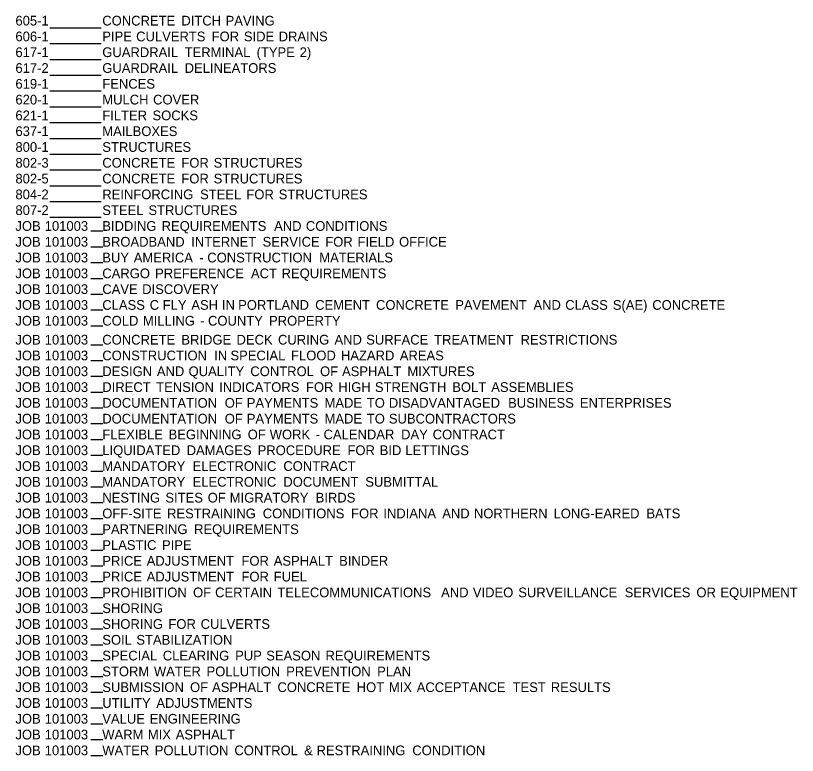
# Model space of a CAD drawing. Extents: x 2713 to 4149, y 471 to 1457.
# Drawn here: x 2714.3 to 3196.9, y 524 to 980.7 of the extents above; entities that cross this region are included whole.
import ezdxf

# ---------------------------------------------------------------- set-up
doc = ezdxf.new("R2010")
doc.units = 0
doc.layers.add('Default', color=7, linetype='Continuous')
doc.layers.add('R_Border', color=7, linetype='Continuous')

msp = doc.modelspace()

# ---------------------------------------------------------------- linework, layer by layer
at = {"layer": 'R_Border'}
for p, q in [((2735.51, 973.16), (2767.2, 973.16)), ((2735.51, 963.41), (2767.2, 963.41)), ((2735.51, 953.66), (2767.2, 953.66)), ((2735.51, 943.91), (2767.2, 943.91)), ((2735.51, 934.16), (2767.2, 934.16)), ((2735.51, 924.41), (2767.2, 924.41)), ((2735.51, 914.66), (2767.2, 914.66)), ((2735.51, 904.91), (2767.2, 904.91)), ((2735.51, 895.16), (2767.2, 895.16)), ((2735.51, 885.41), (2767.2, 885.41)), ((2735.51, 875.66), (2767.2, 875.66)), ((2735.51, 865.91), (2767.2, 865.91)), ((2735.51, 856.16), (2767.2, 856.16)), ((2760.77, 847.73), (2768.21, 847.73)), ((2760.77, 837.98), (2768.21, 837.98)), ((2760.77, 828.23), (2768.21, 828.23)), ((2760.77, 818.48), (2768.21, 818.48)), ((2760.77, 808.73), (2768.21, 808.73)), ((2760.77, 798.98), (2768.21, 798.98)), ((2760.77, 789.23), (2768.21, 789.23)), ((2760.77, 777.55), (2768.21, 777.55)), ((2760.77, 767.8), (2768.21, 767.8)), ((2760.77, 758.05), (2768.21, 758.05)), ((2760.77, 748.3), (2768.21, 748.3)), ((2760.77, 738.55), (2768.21, 738.55)), ((2760.77, 728.8), (2768.21, 728.8)), ((2760.77, 719.05), (2768.21, 719.05)), ((2760.77, 709.3), (2768.21, 709.3)), ((2760.77, 699.55), (2768.21, 699.55)), ((2760.77, 689.8), (2768.21, 689.8)), ((2760.77, 680.05), (2768.21, 680.05)), ((2760.77, 670.3), (2768.21, 670.3)), ((2760.77, 660.55), (2768.21, 660.55)), ((2760.77, 650.8), (2768.21, 650.8)), ((2760.77, 641.05), (2768.21, 641.05)), ((2760.77, 631.3), (2768.21, 631.3)), ((2760.77, 621.55), (2768.21, 621.55)), ((2760.77, 611.8), (2768.21, 611.8)), ((2760.77, 602.05), (2768.21, 602.05)), ((2760.77, 592.3), (2768.21, 592.3)), ((2760.77, 582.55), (2768.21, 582.55)), ((2760.77, 572.8), (2768.21, 572.8)), ((2760.77, 563.05), (2768.21, 563.05)), ((2760.77, 553.3), (2768.21, 553.3)), ((2760.77, 543.55), (2768.21, 543.55)), ((2760.77, 533.8), (2768.21, 533.8)), ((2760.77, 524.05), (2768.21, 524.05))]:
    msp.add_line(p, q, dxfattribs=at)

# ---------------------------------------------------------------- texts
at = {"layer": 'Default'}
for s, p in [('605-1', (2714.22, 974.57)), ('CONCRETE', (2767.84, 974.57)), (' DITCH', (2814.44, 974.57)), (' PAVING', (2841.71, 974.57)), ('606-1', (2714.22, 964.82)), ('PIPE', (2767.84, 964.82)), (' CULVERTS', (2786.5, 964.82)), (' FOR', (2833.11, 964.82)), (' SIDE', (2853.02, 964.82)), (' DRAINS', (2874.47, 964.82)), ('617-1', (2714.22, 955.07)), ('GUARDRAIL', (2767.84, 955.07)), (' TERMINAL', (2816.46, 955.07)), (' (TYPE', (2860.88, 955.07)), (' 2)', (2887.45, 955.07)), ('617-2', (2714.22, 945.32)), ('GUARDRAIL', (2767.84, 945.32)), (' DELINEATORS', (2816.46, 945.32)), ('619-1', (2714.22, 935.57)), ('FENCES', (2767.84, 935.57)), ('620-1', (2714.22, 925.82)), ('MULCH', (2767.84, 925.82)), (' COVER', (2796.97, 925.82)), ('621-1', (2714.22, 916.07)), ('FILTER', (2767.84, 916.07)), (' SOCKS', (2796.61, 916.07)), ('637-1', (2714.22, 906.32)), ('MAILBOXES', (2767.84, 906.32)), ('800-1', (2714.22, 896.57)), ('STRUCTURES', (2767.84, 896.57)), ('802-3', (2714.22, 886.82)), ('CONCRETE', (2767.84, 886.82)), (' FOR', (2814.44, 886.82)), (' STRUCTURES', (2834.35, 886.82)), ('802-5', (2714.22, 877.07)), ('CONCRETE', (2767.84, 877.07)), (' FOR', (2814.44, 877.07)), (' STRUCTURES', (2834.35, 877.07)), ('804-2', (2714.22, 867.32)), ('REINFORCING', (2767.84, 867.32)), (' STEEL', (2826, 867.32)), (' FOR', (2854.59, 867.32)), (' STRUCTURES', (2874.51, 867.32)), ('807-2', (2714.22, 857.57)), ('STEEL', (2767.84, 857.57)), (' STRUCTURES', (2794.1, 857.57)), ('JOB', (2714.22, 847.82)), (' 101003', (2730.08, 847.82)), ('BIDDING', (2767.84, 847.82)), (' REQUIREMENTS', (2802.25, 847.82)), (' AND', (2871.68, 847.82)), (' CONDITIONS', (2891.27, 847.82)), ('JOB', (2714.22, 838.07)), (' 101003', (2730.08, 838.07)), ('BROADBAND', (2767.84, 838.07)), (' INTERNET', (2820.51, 838.07)), (' SERVICE', (2864.59, 838.07)), (' FOR', (2903.27, 838.07)), (' FIELD', (2923.19, 838.07)), (' OFFICE', (2948.82, 838.07)), ('JOB', (2714.22, 828.32)), (' 101003', (2730.08, 828.32)), ('BUY', (2767.84, 828.32)), (' AMERICA', (2785.02, 828.32)), (' -', (2825.56, 828.32)), (' CONSTRUCTION', (2830.42, 828.32)), (' MATERIALS', (2899.59, 828.32)), ('JOB', (2714.22, 818.57)), (' 101003', (2730.08, 818.57)), ('CARGO', (2767.84, 818.57)), (' PREFERENCE', (2798.21, 818.57)), (' ACT', (2857.4, 818.57)), (' REQUIREMENTS', (2876.33, 818.57)), ('JOB', (2714.22, 808.82)), (' 101003', (2730.08, 808.82)), ('CAVE', (2767.84, 808.82)), (' DISCOVERY', (2790.23, 808.82)), ('JOB', (2714.22, 799.07)), (' 101003', (2730.08, 799.07)), ('CLASS', (2767.84, 799.07)), (' C', (2794.9, 799.07)), (' FLY', (2802.94, 799.07)), (' ASH', (2820.58, 799.07)), (' IN', (2839.47, 799.07)), (' PORTLAND', (2849.5, 799.07)), (' CEMENT', (2897.03, 799.07)), (' CONCRETE', (2934.59, 799.07)), (' PAVEMENT', (2983.52, 799.07)), (' AND', (3031.8, 799.07)), (' CLASS', (3051.39, 799.07)), (' S(AE)', (3080.77, 799.07)), (' CONCRETE', (3105.15, 799.07)), ('JOB', (2714.22, 789.32)), (' 101003', (2730.08, 789.32)), ('COLD', (2767.84, 789.32)), (' MILLING', (2790.68, 789.32)), (' -', (2826.02, 789.32)), (' COUNTY', (2830.88, 789.32)), (' PROPERTY', (2868.54, 789.32)), ('JOB', (2714.22, 777.62)), (' 101003', (2730.08, 777.62)), ('CONCRETE', (2767.84, 777.62)), (' BRIDGE', (2814.44, 777.62)), (' DECK', (2848.47, 777.62)), (' CURING', (2874.07, 777.62)), (' AND', (2908.94, 777.62)), (' SURFACE', (2928.52, 777.62)), (' TREATMENT', (2970.47, 777.62)), (' RESTRICTIONS', (3023.86, 777.62)), ('JOB', (2714.22, 767.87)), (' 101003', (2730.08, 767.87)), ('CONSTRUCTION', (2767.84, 767.87)), (' IN', (2834.69, 767.87)), (' SPECIAL', (2844.72, 767.87)), (' FLOOD', (2882.16, 767.87)), (' HAZARD', (2912.92, 767.87)), (' AREAS', (2949.27, 767.87)), ('JOB', (2714.22, 758.12)), (' 101003', (2730.08, 758.12)), ('DESIGN', (2767.84, 758.12)), (' AND', (2799.3, 758.12)), (' QUALITY', (2818.88, 758.12)), (' CONTROL', (2857.02, 758.12)), (' OF', (2900.04, 758.12)), (' ASPHALT', (2913.62, 758.12)), (' MIXTURES', (2953.99, 758.12)), ('JOB', (2714.22, 748.37)), (' 101003', (2730.08, 748.37)), ('DIRECT', (2767.84, 748.37)), (' TENSION', (2798.88, 748.37)), (' INDICATORS', (2837.79, 748.37)), (' FOR', (2891.38, 748.37)), (' HIGH', (2911.29, 748.37)), (' STRENGTH', (2933.9, 748.37)), (' BOLT', (2981.67, 748.37)), (' ASSEMBLIES', (3005.72, 748.37)), ('JOB', (2714.22, 738.62)), (' 101003', (2730.08, 738.62)), ('DOCUMENTATION', (2767.84, 738.62)), (' OF', (2841.21, 738.62)), (' PAYMENTS', (2854.8, 738.62)), (' MADE', (2902.81, 738.62)), (' TO', (2928.92, 738.62)), (' DISADVANTAGED', (2942.51, 738.62)), (' BUSINESS', (3016.14, 738.62)), (' ENTERPRISES', (3060.43, 738.62)), ('JOB', (2714.22, 728.87)), (' 101003', (2730.08, 728.87)), ('DOCUMENTATION', (2767.84, 728.87)), (' OF', (2841.21, 728.87)), (' PAYMENTS', (2854.8, 728.87)), (' MADE', (2902.81, 728.87)), (' TO', (2928.92, 728.87)), (' SUBCONTRACTORS', (2942.51, 728.87)), ('JOB', (2714.22, 719.12)), (' 101003', (2730.08, 719.12)), ('FLEXIBLE', (2767.84, 719.12)), (' BEGINNING', (2806.53, 719.12)), (' OF', (2855.38, 719.12)), (' WORK', (2868.97, 719.12)), (' CALENDAR', (2902.22, 719.12)), (' DAY', (2950.09, 719.12)), (' CONTRACT', (2969.59, 719.12)), (' -', (2897.36, 719.12)), ('JOB', (2714.22, 709.37)), (' 101003', (2730.08, 709.37)), ('LIQUIDATED', (2767.84, 709.37)), (' DAMAGES', (2817.7, 709.37)), (' PROCEDURE', (2861.52, 709.37)), (' FOR', (2916.98, 709.37)), (' BID', (2936.89, 709.37)), (' LETTINGS', (2952.74, 709.37)), ('JOB', (2714.22, 699.62)), (' 101003', (2730.08, 699.62)), ('MANDATORY', (2767.84, 699.62)), (' ELECTRONIC', (2821.35, 699.62)), (' CONTRACT', (2877.38, 699.62)), ('JOB', (2714.22, 689.87)), (' 101003', (2730.08, 689.87)), ('MANDATORY', (2767.84, 689.87)), (' ELECTRONIC', (2821.35, 689.87)), (' DOCUMENT', (2877.38, 689.87)), (' SUBMITTAL', (2927.97, 689.87)), ('JOB', (2714.22, 680.12)), (' 101003', (2730.08, 680.12)), ('NESTING', (2767.84, 680.12)), (' SITES', (2804.58, 680.12)), (' OF', (2830.7, 680.12)), (' MIGRATORY', (2844.29, 680.12)), (' BIRDS', (2897.32, 680.12)), ('JOB', (2714.22, 670.37)), (' 101003', (2730.08, 670.37)), ('OFF-SITE', (2767.84, 670.37)), (' RESTRAINING', (2805.58, 670.37)), (' CONDITIONS', (2864.68, 670.37)), (' FOR', (2919.2, 670.37)), (' INDIANA', (2939.11, 670.37)), (' AND', (2975.46, 670.37)), (' NORTHERN', (2995.04, 670.37)), (' LONG-EARED', (3044.2, 670.37)), (' BATS', (3101.51, 670.37)), ('JOB', (2714.22, 660.62)), (' 101003', (2730.08, 660.62)), ('PARTNERING', (2767.84, 660.62)), (' REQUIREMENTS', (2822.28, 660.62)), ('JOB', (2714.22, 650.87)), (' 101003', (2730.08, 650.87)), ('PLASTIC', (2767.84, 650.87)), (' PIPE', (2802.45, 650.87)), ('JOB', (2714.22, 641.12)), (' 101003', (2730.08, 641.12)), ('PRICE', (2767.84, 641.12)), (' ADJUSTMENT', (2793.02, 641.12)), (' FOR', (2851.54, 641.12)), (' ASPHALT', (2871.45, 641.12)), (' BINDER', (2911.82, 641.12)), ('JOB', (2714.22, 631.37)), (' 101003', (2730.08, 631.37)), ('PRICE', (2767.84, 631.37)), (' ADJUSTMENT', (2793.02, 631.37)), (' FOR', (2851.54, 631.37)), (' FUEL', (2871.45, 631.37)), ('JOB', (2714.22, 621.62)), (' 101003', (2730.08, 621.62)), ('PROHIBITION', (2767.84, 621.62)), (' OF', (2821.65, 621.62)), (' CERTAIN', (2835.24, 621.62)), (' TELECOMMUNICATIONS', (2873.68, 621.62)), (' AND', (2974.79, 621.62)), (' VIDEO', (2994.37, 621.62)), (' SURVEILLANCE', (3022.41, 621.62)), (' SERVICES', (3088.12, 621.62)), (' OR', (3132.41, 621.62)), (' EQUIPMENT', (3147.2, 621.62)), ('JOB', (2714.22, 611.87)), (' 101003', (2730.08, 611.87)), ('SHORING', (2767.84, 611.87)), ('JOB', (2714.22, 602.12)), (' 101003', (2730.08, 602.12)), ('SHORING', (2767.84, 602.12)), (' FOR', (2806.44, 602.12)), (' CULVERTS', (2826.35, 602.12)), ('JOB', (2714.22, 592.37)), (' 101003', (2730.08, 592.37)), ('SOIL', (2767.84, 592.37)), (' STABILIZATION', (2786.65, 592.37)), ('JOB', (2714.22, 582.62)), (' 101003', (2730.08, 582.62)), ('SPECIAL', (2767.84, 582.62)), (' CLEARING', (2802.96, 582.62)), (' PUP', (2847.62, 582.62)), (' SEASON', (2866.82, 582.62)), (' REQUIREMENTS', (2903.41, 582.62)), ('JOB', (2714.22, 572.87)), (' 101003', (2730.08, 572.87)), ('STORM', (2767.84, 572.87)), (' WATER', (2797.48, 572.87)), (' POLLUTION', (2829.97, 572.87)), (' PREVENTION', (2879.13, 572.87)), (' PLAN', (2935.28, 572.87)), ('JOB', (2714.22, 563.12)), (' 101003', (2730.08, 563.12)), ('SUBMISSION', (2767.84, 563.12)), (' OF', (2819.8, 563.12)), (' ASPHALT', (2833.38, 563.12)), (' CONCRETE', (2873.75, 563.12)), (' HOT', (2922.68, 563.12)), (' MIX', (2942.54, 563.12)), (' ACCEPTANCE', (2959.71, 563.12)), (' TEST', (3018.9, 563.12)), (' RESULTS', (3042.49, 563.12)), ('JOB', (2714.22, 553.37)), (' 101003', (2730.08, 553.37)), ('UTILITY', (2767.84, 553.37)), (' ADJUSTMENTS', (2798.98, 553.37)), ('JOB', (2714.22, 543.62)), (' 101003', (2730.08, 543.62)), ('VALUE', (2767.84, 543.62)), (' ENGINEERING', (2794.89, 543.62)), ('JOB', (2714.22, 533.87)), (' 101003', (2730.08, 533.87)), ('WARM', (2767.84, 533.87)), (' MIX', (2793.75, 533.87)), (' ASPHALT', (2810.93, 533.87)), ('JOB', (2714.22, 524.12)), (' 101003', (2730.08, 524.12)), ('WATER', (2767.84, 524.12)), (' POLLUTION', (2798, 524.12)), (' CONTROL', (2847.16, 524.12)), (' &', (2890.18, 524.12)), (' RESTRAINING', (2897.91, 524.12)), (' CONDITION', (2957.01, 524.12))]:
    msp.add_text(s, height=6, dxfattribs=at).set_placement(p)

doc.saveas('drawing.dxf')
